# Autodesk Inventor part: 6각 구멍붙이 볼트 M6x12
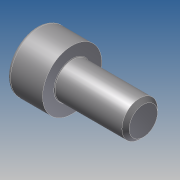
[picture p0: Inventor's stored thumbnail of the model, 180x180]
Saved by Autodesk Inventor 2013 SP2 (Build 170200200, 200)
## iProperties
Created: 2025-06
Part Number: 6각 구멍붙이 볼트 M6x12
Material: Generic
Document SubType Name: Modeling
Designer: i
Density: 1 g/cm^3
Author: i
변환 표준: STEP AP214IS
전처리기: Build: 200, Release: 2013 SP2 Update 6 - Date: Thu 07/17/2014
전송 단위: 밀리미터
불확실성: 0.01
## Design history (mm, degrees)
node "6각 구멍붙이 볼트 M6x121"
body "Solid1"
node "기준1"
